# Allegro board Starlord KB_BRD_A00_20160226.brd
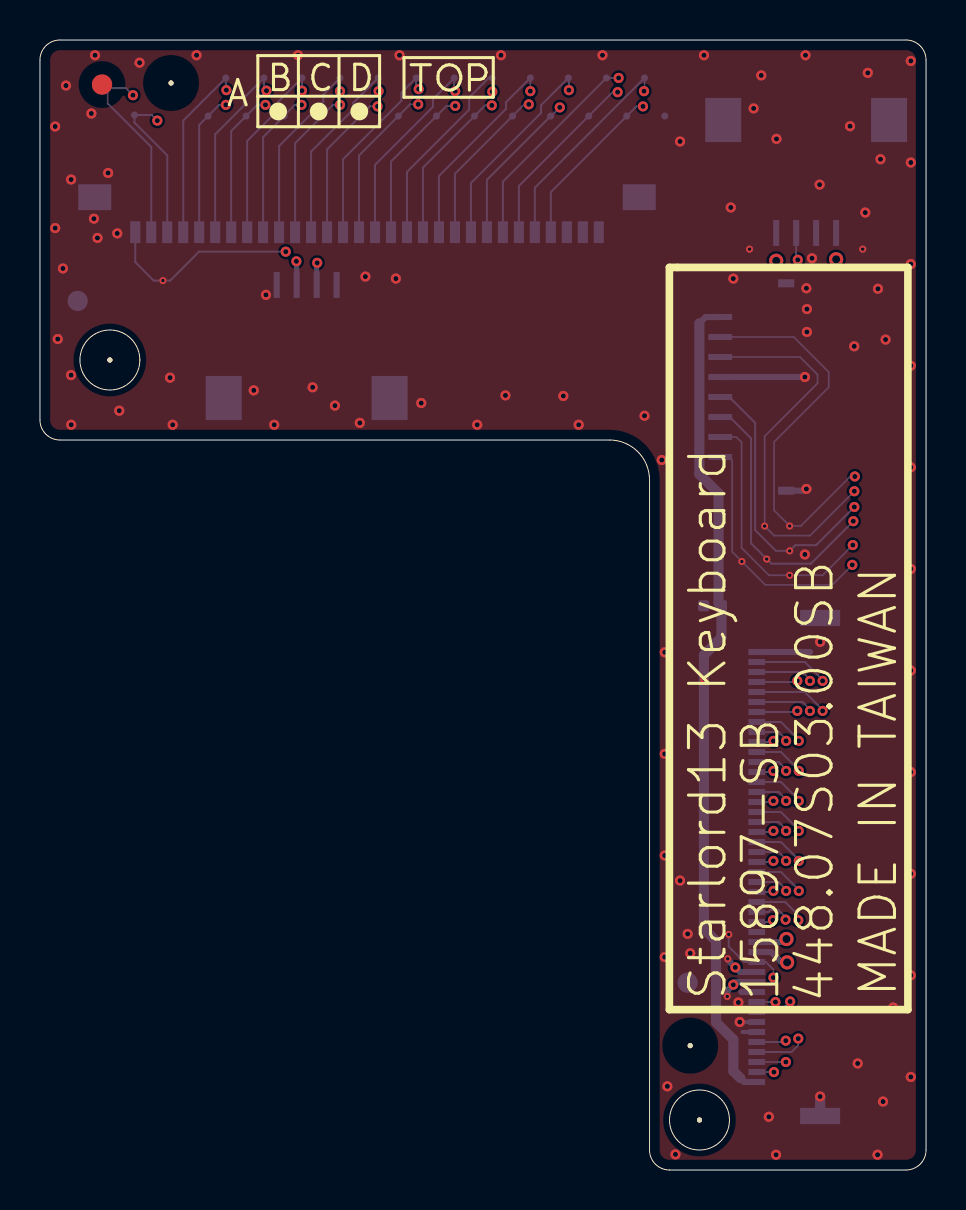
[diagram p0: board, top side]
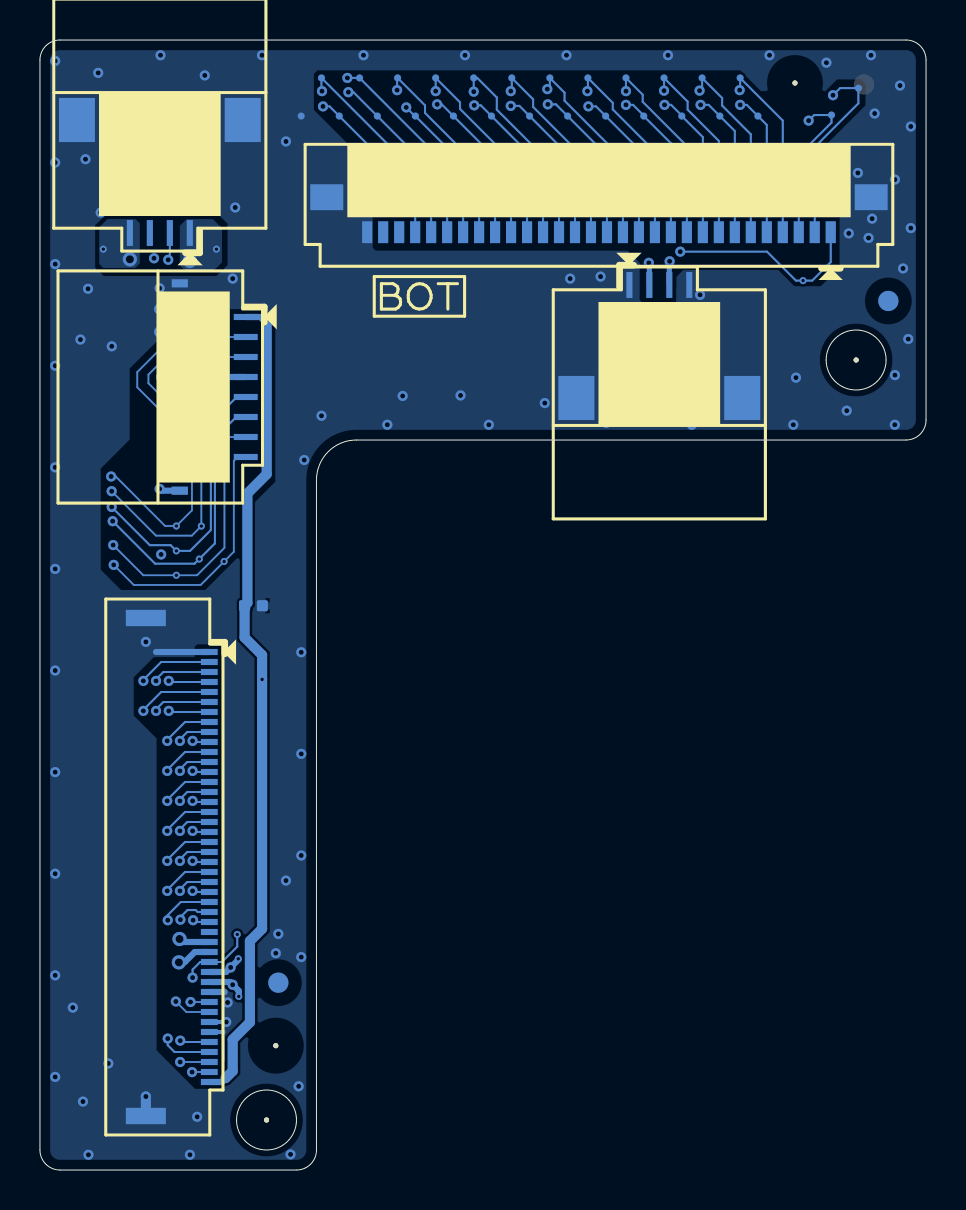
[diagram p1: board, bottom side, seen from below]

Outline 44.35 x 56.5 mm; copper layers: TOP, L2GND, L3, L4, L5VCC, L6, L7GND, BOTTOM. Coordinates in mm from the lower left corner of the outline.
Outline path: 0,55.5 0,37.5 arc(0.29,36.79) 1,36.5 28.51,36.5 arc(29.92,35.91) 30.51,34.5 30.51,1 arc(30.8,0.29) 31.51,0 43.35,0 arc(44.06,0.29) 44.35,1 44.35,55.5 arc(44.06,56.21) 43.35,56.5 1,56.5 arc(0.29,56.21) 0,55.5 ; 2,40.5 arc(3.5,42) 5,40.5 arc(3.5,39) 2,40.5 ; 31.51,2.5 arc(33.01,4) 34.51,2.5 arc(33.01,1) 31.51,2.5

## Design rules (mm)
constraint set DEFAULT: min track width 0.127, pair gap 0.102
net group LED_20MIL: nets BAT_AMBER BAT_WHITE
net group OTHER_4MIL-MWS: nets INT_TP# KB_DET# KB_LED_DET_C PTP_DIS#
net group POWER_15M: nets TP_VDD
net group SMBUS_50: nets I2C0_SCL_R I2C0_SDA_R TPCLK_C TPDATA_C
net group T4_KB-MW: nets KSI0 KSI1 KSI2 KSI3 KSI4 KSI5 KSI6 KSI7 KSO0 KSO1 KSO2 KSO3 KSO4 KSO5 KSO6 KSO7 KSO8 KSO9 KSO10 KSO11 KSO12 KSO13 KSO14 KSO15 KSO16
net group T4_LED-MWS: nets CAP_LED

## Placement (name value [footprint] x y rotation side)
AFTP201  AFTE14P-GP  [AFTE14P-75]  10.32 52.7 180 bottom
AFTP202  AFTE14P-GP  [AFTE14P-75]  3.39 54.09 180 bottom
AFTP203  AFTE14P-GP  [AFTE14P-75]  4.73 52.75 180 bottom
AFTP204  AFTE14P-GP  [AFTE14P-75]  28.35 54.6 180 bottom
AFTP205  AFTE14P-GP  [AFTE14P-75]  9.3 54.6 180 bottom
AFTP206  AFTE14P-GP  [AFTE14P-75]  11.21 54.6 180 bottom
AFTP207  AFTE14P-GP  [AFTE14P-75]  22.64 54.6 180 bottom
AFTP208  AFTE14P-GP  [AFTE14P-75]  8.42 52.7 180 bottom
AFTP209  AFTE14P-GP  [AFTE14P-75]  13.11 54.6 180 bottom
AFTP210  AFTE14P-GP  [AFTE14P-75]  15.02 54.6 180 bottom
AFTP211  AFTE14P-GP  [AFTE14P-75]  20.73 54.6 180 bottom
AFTP212  AFTE14P-GP  [AFTE14P-75]  12.23 52.7 180 bottom
AFTP213  AFTE14P-GP  [AFTE14P-75]  19.85 52.7 180 bottom
AFTP214  AFTE14P-GP  [AFTE14P-75]  14.13 52.7 180 bottom
AFTP215  AFTE14P-GP  [AFTE14P-75]  16.92 54.6 180 bottom
AFTP216  AFTE14P-GP  [AFTE14P-75]  18.83 54.6 180 bottom
AFTP217  AFTE14P-GP  [AFTE14P-75]  16.04 52.7 180 bottom
AFTP218  AFTE14P-GP  [AFTE14P-75]  17.94 52.7 180 bottom
AFTP219  AFTE14P-GP  [AFTE14P-75]  21.75 52.7 180 bottom
AFTP220  AFTE14P-GP  [AFTE14P-75]  26.45 54.6 180 bottom
AFTP221  AFTE14P-GP  [AFTE14P-75]  25.56 52.7 180 bottom
AFTP222  AFTE14P-GP  [AFTE14P-75]  27.47 52.7 180 bottom
AFTP223  AFTE14P-GP  [AFTE14P-75]  30.26 54.6 180 bottom
AFTP224  AFTE14P-GP  [AFTE14P-75]  23.66 52.7 180 bottom
AFTP225  AFTE14P-GP  [AFTE14P-75]  31.28 52.7 180 bottom
AFTP226  AFTE14P-GP  [AFTE14P-75]  29.37 52.7 180 bottom
AFTP227  AFTE14P-GP  [AFTE14P-75]  24.54 54.6 180 bottom
C201  SCD1U16V2KX-3GP  [C402H22]  33.66 28.21 90 bottom
KB1  PTWO-CON30-18-GP  [196528-30041-3]  16.37 48.64 0 bottom
KBBD2  STAR-CON44-GP  [51540-04401-W01]  39.05 15.15 270 bottom
KBBL1  ACES-CON4-66-GP  [50524-00401-001]  38.35 52.5 0 bottom
LED1  ACES-CON4-66-GP  [50524-00401-001]  13.35 38.6 180 bottom
NOREF  -  []  14.71 54.45 0 top
NOREF#2  *  [unnamed#2]  3.11 54.27 0 top
NOREF#3  -  []  20.45 54.63 0 top
NOREF#4  -  [unnamed#2]  6.56 54.35 0 top
NOREF#5  -  [unnamed#2]  3.5 40.5 0 top
NOREF#6  -  [unnamed#2]  32.55 6.22 0 top
NOREF#7  -  []  -3.65 -7.5 0 top
NOREF#8  -  []  -133.09 -45.68 0 top
NOREF#9  -  [unnamed#2]  33.01 2.5 0 top
NOREF#10  *  [unnamed#2]  32.42 9.37 180 bottom
NOREF#11  *  [unnamed#2]  1.89 43.45 180 bottom
NOREF#12  -  []  25.36 43.68 180 bottom
TP1  ACES-CON8-66-GP  [51574-0084N-W01]  37.35 39.15 270 bottom

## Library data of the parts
AFTP201-AFTP227 = AFTE14P-75: tolerance: ZZ.AFT14.101
C201 = C402H22: tolerance: 78.10421.2FL
KB1 = 196528-30041-3: tolerance: 020.K0210.0030
KBBD2 = 51540-04401-W01: tolerance: 20.K0809.044
KBBL1 LED1 = 50524-00401-001: tolerance: 020.K0037.0004
TP1 = 51574-0084N-W01: tolerance: 020.K0151.0008

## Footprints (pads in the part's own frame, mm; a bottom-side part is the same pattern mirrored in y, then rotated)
50524-00401-001
  rect 0.305x1.295 smd: 1(-1.5,5.65) 2(-0.5,5.65) 3(0.5,5.65) 4(1.5,5.65)
  rect 1.803x2.21 smd: 5(-4.15,0) 6(4.15,0)
51540-04401-W01
  rect 0.305x0.838 smd: 1(-10.75,3.175) 2(-10.25,3.175) 3(-9.75,3.175) 4(-9.25,3.175) 5(-8.75,3.175) 6(-8.25,3.175) 7(-7.75,3.175) 8(-7.25,3.175) 9(-6.75,3.175) 10(-6.25,3.175) 11(-5.75,3.175) 12(-5.25,3.175) 13(-4.75,3.175) 14(-4.25,3.175) 15(-3.75,3.175) 16(-3.25,3.175) 17(-2.75,3.175) 18(-2.25,3.175) 19(-1.75,3.175) 20(-1.25,3.175) 21(-0.75,3.175) 22(-0.25,3.175) 23(0.25,3.175) 24(0.75,3.175) 25(1.25,3.175) 26(1.75,3.175) 27(2.25,3.175) 28(2.75,3.175) 29(3.25,3.175) 30(3.75,3.175) 31(4.25,3.175) 32(4.75,3.175) 33(5.25,3.175) 34(5.75,3.175) 35(6.25,3.175) 36(6.75,3.175) 37(7.25,3.175) 38(7.75,3.175) 39(8.25,3.175) 40(8.75,3.175) 41(9.25,3.175) 42(9.75,3.175) 43(10.25,3.175) 44(10.75,3.175)
  rect 0.813x2.007 smd: 45(-12.45,0) 46(12.45,0)
51574-0084N-W01
  rect 0.305x1.194 smd: 1(-3.5,3.3) 2(-2.5,3.3) 3(-1.5,3.3) 4(-0.5,3.3) 5(0.5,3.3) 6(1.5,3.3) 7(2.5,3.3) 8(3.5,3.3)
  rect 0.406x0.813 smd: 9(-5.185,0) 10(5.185,0)
196528-30041-3
  rect 0.508x1.092 smd: 1(-11.6,1.75) 2(-10.8,1.75) 3(-10,1.75) 4(-9.2,1.75) 5(-8.4,1.75) 6(-7.6,1.75) 7(-6.8,1.75) 8(-6,1.75) 9(-5.2,1.75) 10(-4.4,1.75) 11(-3.6,1.75) 12(-2.8,1.75) 13(-2,1.75) 14(-1.2,1.75) 15(-0.4,1.75) 16(0.4,1.75) 17(1.2,1.75) 18(2,1.75) 19(2.8,1.75) 20(3.6,1.75) 21(4.4,1.75) 22(5.2,1.75) 23(6,1.75) 24(6.8,1.75) 25(7.6,1.75) 26(8.4,1.75) 27(9.2,1.75) 28(10,1.75) 29(10.8,1.75) 30(11.6,1.75)
  rect 1.651x1.295 smd: 31(-13.625,0) 32(13.625,0)
AFTE14P-75
  round 0.356 smd: 1(0,0)
C402H22
  custom 0.14x0.14 smd: 1(0,0.445) 2(0,-0.445)
unnamed#2
  round 1.016 smd: (0,0)

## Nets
+5V_KB_BL: KBBD2.30 KBBL1.1
GND: AFTP225.1 C201.2 KB1.30 KB1.31 KB1.32 KBBD2.1 KBBD2.35 KBBD2.38 KBBD2.39 KBBD2.45 KBBD2.46 KBBL1.5 KBBL1.6 LED1.1 LED1.4 LED1.5 LED1.6 TP1.4 TP1.9 TP1.10
BAT_AMBER: KBBD2.33 LED1.2
BAT_WHITE: KBBD2.34 LED1.3
CAP_LED: AFTP226.1 KB1.27 KBBD2.2
I2C0_SCL_R: KBBD2.37 TP1.3
I2C0_SDA_R: KBBD2.36 TP1.2
INT_TP#: KBBD2.40 TP1.5
KB_BL_CTRL#: KBBD2.31 KBBL1.4
KB_DET#: KB1.1 KBBD2.28
KB_LED_DET_C: KBBD2.32 KBBL1.2
KSI0: AFTP212.1 KB1.9 KBBD2.20
KSI1: AFTP201.1 KB1.7 KBBD2.22
KSI2: AFTP208.1 KB1.5 KBBD2.24
KSI3: AFTP209.1 KB1.8 KBBD2.21
KSI4: AFTP205.1 KB1.4 KBBD2.25
KSI5: AFTP206.1 KB1.6 KBBD2.23
KSI6: AFTP203.1 KB1.3 KBBD2.26
KSI7: AFTP202.1 KB1.2 KBBD2.27
KSO0: AFTP207.1 KB1.18 KBBD2.11
KSO1: AFTP211.1 KB1.16 KBBD2.13
KSO2: AFTP213.1 KB1.17 KBBD2.12
KSO3: AFTP218.1 KB1.15 KBBD2.14
KSO4: AFTP214.1 KB1.11 KBBD2.18
KSO5: AFTP210.1 KB1.10 KBBD2.19
KSO6: AFTP217.1 KB1.13 KBBD2.16
KSO7: AFTP215.1 KB1.12 KBBD2.17
KSO8: AFTP216.1 KB1.14 KBBD2.15
KSO9: AFTP204.1 KB1.24 KBBD2.5
KSO10: AFTP223.1 KB1.26 KBBD2.3
KSO11: AFTP222.1 KB1.25 KBBD2.4
KSO12: AFTP219.1 KB1.19 KBBD2.10
KSO13: AFTP220.1 KB1.22 KBBD2.7
KSO14: AFTP221.1 KB1.23 KBBD2.6
KSO15: AFTP224.1 KB1.21 KBBD2.8
KSO16: AFTP227.1 KB1.20 KBBD2.9
PTP_DIS#: KBBD2.41 TP1.6
TP_VDD: C201.1 KBBD2.44 TP1.1
TPCLK_C: KBBD2.43 TP1.8
TPDATA_C: KBBD2.42 TP1.7

Pads without a net: KB1 28 29; KBBD2 29; KBBL1 3

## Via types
v1: diameter 0.356, hole 0.178, TOP to BOTTOM, 13 vias
v2: diameter 0.508, hole 0.254, TOP to BOTTOM, 163 vias
v3: diameter 0.711, hole 0.406, TOP to BOTTOM, 4 vias

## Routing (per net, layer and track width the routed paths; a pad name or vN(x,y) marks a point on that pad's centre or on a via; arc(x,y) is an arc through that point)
+5V_KB_BL: length 39.6
  L3 w1.016: v3(37.36,11.55) 39.28,11.55 40.8,13.07 40.8,26.46 36.85,30.41 v3(36.85,45.46)
  BOTTOM w0.305: KBBD2.30 37.21,11.4 v3(37.36,11.55)
  vias: v1(35.52,46.04)
GND: length 11.3
  BOTTOM w0.203: 35.16,6.9 KBBD2.39 ; KBBD2.38 v2(35.02,7.4)
  BOTTOM w0.305: v2(38.36,34.05) 38.27,33.96 TP1.10 ; 35.1,8.9 KBBD2.35 ; 38.54,25.9 KBBD2.1 ; TP1.4 v2(38.29,39.65)
  BOTTOM w0.508: KBBD2.46 v2(39.05,3.67)
  vias: v2(0.76,52.18) v2(0.76,47.1) v2(0.89,41.55) v2(1.15,45.08) v2(1.3,54.22) v2(1.56,49.52) v2(1.56,39.74) v2(1.56,37.26) v2(2.57,52.82) v2(2.7,47.57) v2(2.76,55.74) v2(2.88,46.6) v2(3.41,49.85) v2(3.87,46.83) v2(3.97,37.97) v2(4.99,55.36) v2(6.51,39.62) v2(6.64,37.26) v2(7.84,55.74) v2(10.7,38.98) v2(11.31,43.76) v2(11.72,37.26) v2(12.92,55.74) v2(13.65,39.13) v2(14.77,38.22) v2(16.01,37.36) v2(16.29,44.67) v2(17.81,44.57) v2(18,55.74) v2(19.08,38.35) v2(21.88,37.26) v2(23.08,55.74) v2(23.3,38.73) v2(26.2,38.7) v2(26.96,37.26) v2(28.16,55.74) v2(30.26,37.71) v2(31.12,35.5) v2(31.27,25.89) v2(31.27,20.81) v2(31.27,15.73) v2(31.27,10.65) v2(31.4,4.18) v2(31.81,0.78) v2(32.04,51.43) v2(32.04,14.47) v2(32.42,11.8) v2(32.55,10.84) v2(33.24,55.74) v2(34.58,48.13) v2(34.7,44.57) v2(34.96,8.37) v2(35.72,53.08) v2(36.1,54.73) v2(36.48,2.66) v2(36.86,51.55) v2(36.84,0.76) v2(38.29,30.78) v2(38.32,55.74) v2(38.36,44.09) v2(38.39,43.05) v2(38.39,41.9) v2(38.64,45.59) v2(39.02,49.27) v2(39.05,26.41) v2(40.55,52.19) v2(40.76,41.18) v2(40.93,5.33) v2(41.31,47.87) v2(41.44,54.86) v2(41.94,44.06) v2(41.92,0.76) v2(42.07,50.54) v2(42.2,3.42) v2(42.32,41.52) v2(42.71,8.12) v2(43.59,55.45) v2(43.59,50.37) v2(43.59,45.29) v2(43.59,40.21) v2(43.59,35.13) v2(43.59,30.05) v2(43.59,24.97) v2(43.59,19.89) v2(43.59,14.81) v2(43.59,9.73) v2(43.59,4.65)
BAT_AMBER: length 53.9
  L3 w0.508: v2(34.81,10.13) 34.59,10.34 34.59,35.45 30,40.05 17.88,40.05 13.88,44.05 v2(13.88,45.36)
  BOTTOM w0.254: LED1.2 13.85,45.33 v2(13.88,45.36)
  BOTTOM w0.305: KBBD2.33 35.03,9.9 v2(34.81,10.13) 34.42,10.51 v1(34.42,10.56)
BAT_WHITE: length 55.5
  L3 w0.508: v2(12.83,45.43) 12.83,44.09 17.51,39.41 29.73,39.41 33.87,35.28 33.87,10.1 v2(34.7,9.26)
  BOTTOM w0.254: v2(12.83,45.43) 12.85,45.42 LED1.3
  BOTTOM w0.305: v1(34.4,8.68) 34.4,8.96 v2(34.7,9.26) 34.84,9.4 KBBD2.34
CAP_LED: length 44.6
  L6 w0.102: v2(39.17,24.46) 37.83,25.8 37.83,39.74 30.18,47.39 v2(30.18,53.18)
  BOTTOM w0.102: v2(39.17,24.46) 39.17,24.51 38.28,25.4 KBBD2.2 ; v2(30.18,53.18) 29.85,53.18 AFTP226.1 25.57,48.9 KB1.27
I2C0_SCL_R: length 49.8
  L6 w0.102: v2(40.76,33.94) 39.96,33.14 39.96,29.83 40.98,28.82 40.98,10.56 39.07,8.65 37.78,8.65 v2(37.55,8.43)
  BOTTOM w0.089: KBBD2.37 37.02,7.9 v2(37.55,8.43) ; v2(40.76,33.94) 38.54,31.72 36.75,31.72 v1(36.27,32.2) 36.27,36.69 38.92,39.34 38.92,39.77 38.04,40.65 TP1.3
I2C0_SDA_R: length 50.1
  L6 w0.102: v2(36.81,8.4) 36.84,8.4 37.58,9.14 38.87,9.14 40.5,10.76 40.5,28.62 39.48,29.63 39.48,33.37 v2(40.79,34.68)
  BOTTOM w0.089: KBBD2.36 v2(36.81,8.4) ; v2(40.79,34.68) 40.56,34.68 38.08,32.2 v1(37.52,32.2) 36.74,32.98 36.74,36.4 39.48,39.13 39.48,39.9 37.73,41.65 TP1.2
INT_TP#: length 46.6
  L6 w0.102: v2(37.33,6.47) 37.77,6.03 38.83,6.03 42.63,9.83 42.63,31.28 v2(40.76,33.15)
  BOTTOM w0.102: v2(40.76,33.15) 38.85,31.24 37.81,31.24 v1(37.52,30.96) 36.84,30.96 35.8,32 35.8,37.36 34.5,38.65 TP1.5 ; KBBD2.40 37.26,6.4 v2(37.33,6.47)
KB_BL_CTRL#: length 41.7
  L3 w1.016: v3(37.4,10.38) 40.01,10.38 42.07,12.44 42.07,27.04 39.35,29.76 39.35,45.04 v3(39.85,45.54)
  BOTTOM w0.305: v3(37.4,10.38) 37.37,10.41 37.09,10.41 36.6,10.9 KBBD2.31
  vias: v1(41.18,46.04)
KB_DET#: length 61.2
  L6 w0.102: v2(36.69,12.49) 31.88,17.29 31.88,37.28 22.77,46.4 12.78,46.4 v2(12.3,45.92)
  BOTTOM w0.102: v2(12.3,45.92) 7.96,45.92 6.51,44.47 v1(6.15,44.47) 5.7,44.47 4.77,45.4 KB1.1 ; v2(36.69,12.49) 36.6,12.4 KBBD2.28
KB_LED_DET_C: length 44.2
  L6 w0.102: v2(36.71,9.62) 38.67,9.62 39.84,10.79 39.84,28.46 39,29.3 39,44.44 v2(37.93,45.51)
  BOTTOM w0.102: v2(36.71,9.62) 36.71,10.02 36.33,10.4 KBBD2.32 35.24,10.4 34.48,11.17 v1(34.48,11.78) ; KBBL1.2 37.85,45.59 v2(37.93,45.51)
KSI0: length 61.6
  L6 w0.102: v2(37.98,15.45) 37.11,16.33 36.73,16.33 33.71,19.34 33.71,38.04 23.22,48.53 17.43,48.53 13.09,52.88 v2(13.09,53.26)
  BOTTOM w0.102: v2(37.98,15.45) 37.98,15.51 37.09,16.4 KBBD2.20 ; KB1.9 11.17,51.64 AFTP212.1 12.23,52.72 12.76,53.26 v2(13.09,53.26)
KSI1: length 60.4
  L6 w0.102: v2(11.29,53.26) 16.54,48 23.11,48 33.26,37.85 33.26,18.91 v2(36.71,15.45)
  BOTTOM w0.102: v2(11.29,53.26) 10.88,53.26 AFTP201.1 9.57,51.95 KB1.7 ; KBBD2.22 36.66,15.4 v2(36.71,15.45)
KSI2: length 64.4
  L6 w0.102: v2(37.35,13.95) 36.91,14.39 36.84,14.39 32.8,18.43 32.8,37.66 22.99,47.47 15.1,47.47 v2(9.3,53.26)
  BOTTOM w0.102: KB1.5 7.97,52.25 AFTP208.1 8.97,53.26 v2(9.3,53.26) ; KBBD2.24 36.98,14.4 37.32,14.06 37.32,13.98 v2(37.35,13.95)
KSI3: length 63.5
  L6 w0.102: v2(37.35,15.45) 36.7,16.1 36.63,16.1 33.48,19.25 33.48,37.94 23.18,48.25 17.39,48.25 12.66,52.98 12.66,53.51 v2(13.11,53.97)
  BOTTOM w0.102: v2(37.35,15.45) 37.32,15.48 37.32,15.56 36.98,15.9 KBBD2.21 ; KB1.8 10.37,51.45 11.93,53.02 11.93,53.42 AFTP209.1 v2(13.11,53.97)
KSI4: length 66.8
  L6 w0.102: v2(36.71,13.95) 32.57,18.09 32.57,37.57 22.97,47.16 14.47,47.16 8.87,52.76 8.87,53.54 v2(9.33,53.99)
  BOTTOM w0.102: KB1.4 7.17,52.47 AFTP205.1 9.3,54.02 v2(9.33,53.99) ; KBBD2.25 35.88,13.9 36.66,13.9 v2(36.71,13.95)
KSI5: length 67.6
  L6 w0.102: v2(11.34,53.97) 10.85,53.49 10.85,53.08 16.19,47.74 23.04,47.74 33.03,37.75 33.03,18.53 36.53,15.02 36.91,15.02 v2(37.98,13.95)
  BOTTOM w0.102: v2(11.34,53.97) 11.21,54.09 AFTP206.1 10.21,53.6 10.21,53.22 8.77,51.78 KB1.6 ; v2(37.98,13.95) 37.98,14.01 37.09,14.9 35.88,14.9 KBBD2.23
KSI6: length 70.6
  L6 w0.102: v2(5.88,52.47) 8.77,52.47 14.31,46.93 22.88,46.93 32.34,37.47 32.34,17.71 36.6,13.45 36.99,13.45 37.75,12.7 37.75,12.69 v2(37.95,12.49)
  BOTTOM w0.102: v2(5.88,52.47) 5.6,52.75 AFTP203.1 4.73,52.37 6.37,50.73 KB1.3 ; KBBD2.26 37.3,13.4 37.95,12.74 v2(37.95,12.49)
KSI7: length 73.1
  L6 w0.102: v2(4.66,53.74) 5.19,53.21 5.19,52.52 5.7,52.01 8.77,52.01 14.16,46.63 22.86,46.63 32.11,37.38 32.11,36.16 32.11,36.16 32.11,17.47 36.36,13.23 36.61,13.23 v2(37.32,12.52)
  BOTTOM w0.102: KB1.2 5.57,51.15 3.39,53.33 AFTP202.1 4.3,54.09 v2(4.66,53.74) ; v2(37.32,12.52) 37.32,12.64 36.97,13 36.56,13 36.46,12.9 KBBD2.27
KSO0: length 53.7
  L6 w0.102: v2(37.98,19.95) 37.24,20.69 36.86,20.69 35.77,21.78 35.77,38.89 22.16,52.51 22.16,53.43 v2(22.64,53.92)
  BOTTOM w0.102: v2(22.64,53.92) AFTP207.1 22.46,54.6 21.48,53.62 21.48,53.02 18.37,49.9 KB1.18 ; KBBD2.11 35.88,20.9 37.09,20.9 37.98,20.01 v2(37.98,19.95)
KSO1: length 52.2
  L6 w0.102: v2(20.78,53.94) 20.35,53.51 20.35,53.03 23.25,50.13 23.88,50.13 35.31,38.7 35.31,21.35 v2(36.71,19.95)
  BOTTOM w0.102: KB1.16 16.77,50.26 19.67,53.16 19.67,53.54 AFTP211.1 20.73,53.99 v2(20.78,53.94) ; v2(36.71,19.95) 36.66,19.9 35.88,19.9 KBBD2.13
KSO2: length 50
  L6 w0.102: v2(20.78,53.21) 21.13,53.21 35.54,38.8 35.54,21.69 36.77,20.47 36.84,20.47 v2(37.35,19.95)
  BOTTOM w0.102: KB1.17 17.57,50.42 AFTP213.1 20.35,53.21 v2(20.78,53.21) ; v2(37.35,19.95) 37.32,19.98 37.32,20.06 36.98,20.4 KBBD2.12
KSO3: length 54.2
  L6 w0.102: v2(18.93,53.28) 22.31,49.9 23.79,49.9 35.09,38.61 35.09,20.97 36.86,19.2 37.24,19.2 v2(37.98,18.45)
  BOTTOM w0.102: KBBD2.14 37.09,19.4 37.98,18.51 v2(37.98,18.45) ; KB1.15 15.97,50.73 AFTP218.1 18.52,53.28 v2(18.93,53.28)
KSO4: length 57.6
  L6 w0.102: v2(37.35,16.95) 36.55,17.75 36.48,17.75 34.17,20.06 34.17,38.23 23.41,48.99 18.68,48.99 15.02,52.65 v2(15.02,53.26)
  BOTTOM w0.102: v2(37.35,16.95) 37.32,16.98 37.32,17.06 36.98,17.4 KBBD2.18 ; v2(15.02,53.26) 14.66,53.26 14.13,52.72 AFTP214.1 12.77,51.34 KB1.11
KSO5: length 59.6
  L6 w0.102: v2(36.71,16.95) 33.94,19.72 33.94,38.13 23.31,48.76 18.58,48.76 14.59,52.76 14.59,53.51 v2(15.02,53.94)
  BOTTOM w0.102: KB1.10 11.97,51.2 14.18,53.41 14.18,53.76 AFTP210.1 v2(15.02,53.94) ; v2(36.71,16.95) 36.66,16.9 35.88,16.9 KBBD2.19
KSO6: length 53.1
  L6 w0.102: v2(16.9,53.18) 20.63,49.45 23.6,49.45 34.63,38.42 34.63,20.54 v2(36.71,18.45)
  BOTTOM w0.102: KB1.13 14.37,51.03 AFTP217.1 16.52,53.18 v2(16.9,53.18) ; KBBD2.16 36.66,18.4 v2(36.71,18.45)
KSO7: length 60.5
  L6 w0.102: v2(37.98,16.95) 36.96,17.98 36.58,17.98 34.4,20.16 34.4,38.32 23.5,49.22 20.25,49.22 16.47,53 16.47,53.46 v2(16.95,53.94)
  BOTTOM w0.102: KBBD2.17 35.88,17.9 37.09,17.9 37.98,17.01 v2(37.98,16.95) ; v2(16.95,53.94) 16.92,53.97 AFTP215.1 15.68,53.36 15.68,53.03 13.57,50.92 KB1.12
KSO8: length 56.2
  L6 w0.102: v2(18.96,54.04) 18.5,53.59 18.5,53.1 21.93,49.68 23.69,49.68 34.86,38.51 34.86,20.87 36.76,18.97 36.83,18.97 v2(37.35,18.45)
  BOTTOM w0.102: v2(37.35,18.45) 37.32,18.48 37.32,18.56 36.98,18.9 KBBD2.15 ; KB1.14 15.17,50.54 18.09,53.46 18.09,53.87 AFTP216.1 18.83,54.17 v2(18.96,54.04)
KSO9: length 50.9
  L6 w0.102: v2(28.96,54.6) 28.28,53.92 28.28,48.32 37.14,39.46 37.14,24.61 37.96,23.79 38.34,23.79 v2(39.17,22.95)
  BOTTOM w0.102: v2(28.96,54.6) AFTP204.1 23.17,49.42 KB1.24 ; KBBD2.5 38.28,23.9 39.17,23.01 v2(39.17,22.95)
KSO10: length 46.9
  L6 w0.102: v2(38.54,24.46) 37.6,25.39 37.6,39.65 29.67,47.57 29.67,53.38 v2(30.23,53.94)
  BOTTOM w0.102: v2(38.54,24.46) 38.51,24.48 38.51,24.56 38.17,24.9 KBBD2.3 ; v2(30.23,53.94) 30.26,53.97 AFTP223.1 24.77,49.11 KB1.26
KSO11: length 44.4
  L6 w0.102: v2(28.91,53.89) 28.91,48.01 37.37,39.55 37.37,24.99 v2(37.9,24.46)
  BOTTOM w0.102: v2(28.91,53.89) 28.66,53.89 AFTP222.1 23.97,49.2 KB1.25 ; KBBD2.4 35.88,24.4 37.85,24.4 v2(37.9,24.46)
KSO12: length 46.4
  L6 w0.102: v2(36.71,21.45) 36,22.17 36,38.99 22.61,52.38 22.61,53.23 v2(22.61,53.23)
  BOTTOM w0.102: v2(36.71,21.45) 36.66,21.4 KBBD2.10 ; v2(22.61,53.23) 22.28,53.23 AFTP219.1 19.17,50.12 KB1.19
KSO13: length 49.1
  L6 w0.102: v2(26.47,53.99) 26.17,53.99 25.53,53.36 25.53,50.42 36.69,39.27 36.69,24.17 v2(37.9,22.95)
  BOTTOM w0.102: v2(26.47,53.99) 26.47,54.58 AFTP220.1 25.08,53.23 25.08,52.85 21.57,49.35 KB1.22 ; v2(37.9,22.95) 37.85,22.9 KBBD2.7
KSO14: length 46.1
  L6 w0.102: v2(26.02,53.13) 26.02,50.26 36.91,39.37 36.91,24.51 37.86,23.56 37.93,23.56 v2(38.54,22.95)
  BOTTOM w0.102: KBBD2.6 35.88,23.4 38.17,23.4 38.51,23.06 38.51,22.98 v2(38.54,22.95) ; v2(26.02,53.13) 25.59,52.7 AFTP221.1 22.37,49.51 KB1.23
KSO15: length 48
  L6 w0.102: v2(37.98,21.45) 36.46,22.98 36.46,39.18 24.47,51.16 v2(24.47,53.28)
  BOTTOM w0.102: v2(37.98,21.45) 37.98,21.51 37.09,22.4 KBBD2.8 ; v2(24.47,53.28) 24.24,53.28 AFTP224.1 20.77,49.81 KB1.21
KSO16: length 50.2
  L6 w0.102: v2(24.54,53.94) 24.52,53.94 24.04,53.46 24.04,51.27 36.23,39.08 36.23,22.57 v2(37.35,21.45)
  BOTTOM w0.102: KB1.20 19.97,49.7 23.32,53.06 23.32,53.38 AFTP227.1 v2(24.54,53.94) ; v2(37.35,21.45) 37.32,21.48 37.32,21.56 36.98,21.9 KBBD2.9
PTP_DIS#: length 45.3
  L6 w0.102: v2(40.71,32.44) 42.43,30.72 42.43,9.91 39.08,6.57 v2(37.96,6.57)
  BOTTOM w0.102: v2(40.71,32.44) 38.58,30.31 36.62,30.31 36.38,30.55 v1(36.38,30.55) 35.59,31.33 35.59,36.58 34.53,37.65 TP1.6 ; KBBD2.41 37.61,5.9 37.96,6.24 v2(37.96,6.57)
TP_VDD: length 41.4
  BOTTOM w0.305: TP1.1 33.32,42.65 33,42.33 ; 35.06,4.59 35.25,4.4 KBBD2.44
  BOTTOM w0.508: 35.06,4.59 34.7,4.95 34.7,6.52 33.84,7.38 33.84,11.45 33.23,12.06 v1(33.23,24.53) 33.23,25.75 34.11,26.62 C201.1 33.97,28.35 33.97,33.83 33,34.79 33,42.33
TPCLK_C: length 42.1
  L6 w0.102: v2(40.66,30.26) 41.46,29.45 41.46,10.36 38.92,7.82 37.22,7.82 36.41,7 36.41,5.23 v2(36.74,4.9)
  BOTTOM w0.089: KBBD2.43 36.73,4.9 v2(36.74,4.9) ; v2(40.66,30.26) 39.66,29.25 36.3,29.25 v1(35.13,30.43) 34.65,30.91 34.65,35.46 34.45,35.65 TP1.8
TPDATA_C: length 44.3
  L6 w0.102: v2(40.68,31.25) 41.94,29.99 41.94,10.16 39.12,7.33 38.72,7.33 37.42,7.33 36.9,6.81 36.9,5.84 v2(37.33,5.4)
  BOTTOM w0.089: v2(40.68,31.25) 39.17,29.74 v1(37.52,29.74) 36.49,29.74 35.12,31.11 35.12,36.38 34.85,36.65 TP1.7 ; KBBD2.42 v2(37.33,5.4)

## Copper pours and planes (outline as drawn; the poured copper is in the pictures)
+5V_KB_BL on BOTTOM: 35.69,47.54 37.02,47.54 37.35,47.21 37.35,45.23 37.04,44.93 35.69,44.93 35.24,45.38 35.24,47.08
GND on TOP, L2GND, L5VCC, L7GND: 31.51,0.51 31.16,0.65 31.02,1 31.02,34.5 30.28,36.27 28.51,37.01 1,37.01 0.65,37.15 0.51,37.5 0.51,55.5 0.65,55.85 1,55.99 43.35,55.99 43.7,55.85 43.84,55.5 43.84,1 43.7,0.65 43.35,0.51
GND on BOTTOM: 31.51,0.51 31.16,0.65 31.02,1 31.02,34.5 30.28,36.27 28.51,37.01 1,37.01 0.65,37.15 0.51,37.5 0.51,55.5 0.65,55.85 1,55.99 43.35,55.99 43.7,55.85 43.84,55.5 43.84,1 43.7,0.65 43.35,0.51 ; 6 cut-outs
GND on L6: 31.51,0.51 31.16,0.65 31.02,1 31.02,34.5 30.28,36.27 28.51,37.01 1,37.01 0.65,37.15 0.51,37.5 0.51,55.5 0.65,55.85 1,55.99 43.35,55.99 43.7,55.85 43.84,55.5 43.84,1 43.7,0.65 43.35,0.51 ; 1 cut-out
KB_BL_CTRL# on BOTTOM: 39.56,47.54 40.98,47.54 41.38,47.14 41.38,45.31 41.18,45.1 39.58,45.1 39.35,45.33 39.35,47.34

Small or netless copper shapes (teardrops, artwork), in the pictures only: 1 on L3

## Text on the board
Ref Des/Silkscreen Top: Starlord13 Keyboard | 15897-SB | 448.07S03.00SB | MADE IN TAIWAN
User.31: ByImpedance:100.0@_REF_L1=("nil(L1)")|_REF_L6=("4.0/10.0(L6)")|Type="DP"|_REF_L4=("4.0/6.5(L4)")|_REF_L3=("4.0/6.5(L3)" "4.0/10.0(L3)")|imp="100.0"|_REF_L8=("nil(L8)") | ByImpedance:33.0@_REF_L1=("8.0(L1)")|_REF_L6=("9.0(L6)")|Type="SE"|_REF_L4=("11.0(L4)")|_REF_L3=("11.0(L3)" "9.0(L3)")|imp="33.0"|_REF_L8=("8.0(L8)") | ByImpedance:35.0@_REF_L1=("7.5(L1)")|_REF_L6=("8.5(L6)")|Type="SE"|_REF_L4=("10.0(L4)")|_REF_L3=("10.0(L3)" "8.5(L3)")|imp="35.0"|_REF_L8=("7.5(L8)") | ByImpedance:37.5@_REF_L1=("6.5(L1)")|_REF_L6=("7.5(L6)")|Type="SE"|_REF_L4=("9.0(L4)")|_REF_L3=("7.5(L3)" "9.0(L3)")|imp="37.5"|_REF_L8=("6.5(L8)") | ByImpedance:40.0@_REF_L1=("6.0(L1)")|_REF_L6=("6.5(L6)")|Type="SE"|_REF_L4=("8.0(L4)")|_REF_L3=("6.5(L3)" "8.0(L3)")|imp="40.0"|_REF_L8=("6.0(L8)") | ByImpedance:45.0@_REF_L1=("4.5(L1)")|_REF_L6=("5.0(L6)")|Type="SE"|_REF_L4=("6.5(L4)")|_REF_L3=("6.5(L3)" "5.0(L3)")|imp="45.0"|_REF_L8=("4.5(L8)") | ByImpedance:50.0@_REF_L1=("3.5(L1)")|_REF_L6=("4.0(L6)")|Type="SE"|_REF_L4=("5.0(L4)")|_REF_L3=("4.0(L3)" "5.0(L3)")|imp="50.0"|_REF_L8=("3.5(L8)") | ByImpedance:55.0@_REF_L1=("nil(L1)")|_REF_L6=("nil(L6)")|Type="SE"|_REF_L4=("4.0(L4)")|_REF_L3=("4.0(L3)")|imp="55.0"|_REF_L8=("nil(L8)") | ByImpedance:60.0@_REF_L1=("7.5/4.0(L1)")|_REF_L6=("9.5/4.5(L6)")|Type="DP"|_REF_L4=("10.5/4.5(L4)")|_REF_L3=("10.5/4.5(L3)" "9.5/4.5(L3)")|imp="60.0"|_REF_L8=("7.5/4.0(L8)") | ByImpedance:63.0@_REF_L1=("7.0/4.5(L1)")|_REF_L6=("8.5/4.0(L6)")|Type="DP"|_REF_L4=("9.5/4.0(L4)")|_REF_L3=("8.5/4.0(L3)" "9.5/4.0(L3)")|imp="63.0"|_REF_L8=("7.0/4.5(L8)") | ByImpedance:70.0@_REF_L1=("6.0/5.0(L1)")|_REF_L6=("7.0/5.0(L6)")|Type="DP"|_REF_L4=("8.5/5.0(L4)")|_REF_L3=("7.0/5.0(L3)" "8.5/5.0(L3)")|imp="70.0"|_REF_L8=("6.0/5.0(L8)") | ByImpedance:72.0@_REF_L1=("5.5/4.5(L1)")|_REF_L6=("6.5/4.5(L6)")|Type="DP"|_REF_L4=("7.5/5.0(L4)")|_REF_L3=("7.5/5.0(L3)" "6.5/4.5(L3)")|imp="72.0"|_REF_L8=("5.5/4.5(L8)") | ByImpedance:75.0@_REF_L1=("5.0/4.5(L1)")|_REF_L6=("6.0/4.5(L6)")|Type="DP"|_REF_L4=("7.0/5.0(L4)")|_REF_L3=("7.0/5.0(L3)" "6.0/4.5(L3)")|imp="75.0"|_REF_L8=("5.0/4.5(L8)") | ByImpedance:80.0@_REF_L1=("4.5/5.0(L1)")|_REF_L6=("5.5/5.0(L6)")|Type="DP"|_REF_L4=("6.0/5.0(L4)")|_REF_L3=("5.5/5.0(L3)" "6.0/5.0(L3)")|imp="80.0"|_REF_L8=("4.5/5.0(L8)") | ByImpedance:83.0@_REF_L1=("3.5/4.0(L1)")|_REF_L6=("5.0/4.0(L6)")|Type="DP"|_REF_L4=("5.5/4.5(L4)")|_REF_L3=("5.5/4.5(L3)" "5.0/4.0(L3)")|imp="83.0"|_REF_L8=("3.5/4.0(L8)") | ByImpedance:85.0@_REF_L1=("4.0/5.0(L1)")|_REF_L6=("5.0/5.5(L6)")|Type="DP"|_REF_L4=("5.5/5.0(L4)")|_REF_L3=("5.5/5.0(L3)" "5.0/5.5(L3)")|imp="85.0"|_REF_L8=("4.0/5.0(L8)") | ByImpedance:88.0@_REF_L1=("4.0/7.0(L1)")|_REF_L6=("4.0/4.0(L6)")|Type="DP"|_REF_L4=("5.0/5.0(L4)")|_REF_L3=("4.0/4.0(L3)" "5.0/5.0(L3)")|imp="88.0"|_REF_L8=("4.0/7.0(L8)") | ByImpedance:90.0@_REF_L1=("4.0/8.0(L1)" "3.5/6.0(L1)")|_REF_L6=("4.0/4.5(L6)")|Type="DP"|_REF_L4=("5.0/6.0(L4)")|_REF_L3=("5.0/6.0(L3)" "4.0/4.5(L3)")|imp="90.0"|_REF_L8=("4.0/8.0(L8)" "3.5/6.0(L8)") | LayerIndex:nil | Source:8-1.0-16f.xls | artWorks:("_REF_L3" "_REF_L6" "_REF_L4" "_REF_L8" "_REF_L1") | gtImpOutlineUsed:BOARD GEOMETRY/OUTLINE
User.32: Board Accuracy Check,Dec 02 10:44:27 2015,Passed | Dummy-Static-No Shape On Layer Check,Dec 02 10:44:27 2015,Passed | Split Plane Check,Oct 21 09:39:32 2015,Passed
User.34: This gerber is just for your reference to find the DP impedance traces in layer L1. | DP IMPEDANCE TABLE: L1 | * - Denotes that this Impedance | is NOT used | IMP(Ohm) | *60.0 | *63.0 | *70.0 | *72.0 | *75.0 | *80.0 | *83.0 | *85.0 | *88.0 | *90.0 | *100.0 | WIDTH(mils) | 7.5/4.0 | 7.0/4.5 | 6.0/5.0 | 5.5/4.5 | 5.0/4.5 | 4.5/5.0 | 3.5/4.0 | 4.0/5.0 | 4.0/7.0 | 4.0/8.0 | 3.5/6.0 | nil | TYPE | DP
User.36: This gerber is just for your reference to find the SE impedance traces in layer L1. | SE IMPEDANCE TABLE: L1 | * - Denotes that this Impedance | is NOT used | IMP(Ohm) | *33.0 | *35.0 | *37.5 | *40.0 | *45.0 | 50.0 | *55.0 | WIDTH(mils) | 8.0 | 7.5 | 6.5 | 6.0 | 4.5 | 3.5 | nil | TYPE | SE
User.38: This gerber is just for your reference to find the DP impedance traces in layer L3. | DP IMPEDANCE TABLE: L3 | * - Denotes that this Impedance | is NOT used | IMP(Ohm) | *60.0 | *63.0 | *70.0 | *72.0 | *75.0 | *80.0 | *83.0 | *85.0 | *88.0 | *90.0 | *100.0 | WIDTH(mils) | 10.5/4.5 | 9.5/4.5 | 8.5/4.0 | 9.5/4.0 | 7.0/5.0 | 8.5/5.0 | 7.5/5.0 | 6.5/4.5 | 6.0/4.5 | 5.5/5.0 | 6.0/5.0 | 5.5/4.5 | 5.0/4.0 | 5.0/5.5 | 4.0/4.0 | 5.0/5.0 | 5.0/6.0 | 4.0/4.5 | 4.0/6.5 | 4.0/10.0 | TYPE | DP
User.40: This gerber is just for your reference to find the SE impedance traces in layer L3. | SE IMPEDANCE TABLE: L3 | * - Denotes that this Impedance | is NOT used | IMP(Ohm) | *33.0 | *35.0 | *37.5 | *40.0 | *45.0 | *50.0 | *55.0 | WIDTH(mils) | 11.0 | 9.0 | 10.0 | 8.5 | 7.5 | 6.5 | 8.0 | 5.0 | 4.0 | TYPE | SE
User.42: This gerber is just for your reference to find the DP impedance traces in layer L4. | DP IMPEDANCE TABLE: L4 | * - Denotes that this Impedance | is NOT used | IMP(Ohm) | *60.0 | *63.0 | *70.0 | *72.0 | *75.0 | *80.0 | *83.0 | *85.0 | *88.0 | *90.0 | *100.0 | WIDTH(mils) | 10.5/4.5 | 9.5/4.0 | 8.5/5.0 | 7.5/5.0 | 7.0/5.0 | 6.0/5.0 | 5.5/4.5 | 5.5/5.0 | 5.0/5.0 | 5.0/6.0 | 4.0/6.5 | TYPE | DP
User.44: This gerber is just for your reference to find the SE impedance traces in layer L4. | SE IMPEDANCE TABLE: L4 | * - Denotes that this Impedance | is NOT used | IMP(Ohm) | *33.0 | *35.0 | *37.5 | *40.0 | *45.0 | *50.0 | *55.0 | WIDTH(mils) | 11.0 | 10.0 | 9.0 | 8.0 | 6.5 | 5.0 | 4.0 | TYPE | SE
User.45: Note:Refer to DRILL layer for ELLIPSE drill direction | FIGURE | SIZE | 10.0 | 16.0 | 86.0 | 119.0 | DRILL CHART: TOP to BOTTOM | ALL UNITS ARE IN MILS | PLATED | NON-PLATED | QTY | 194 | 4 | 2 | This gerber is just for your reference to find the SE impedance traces in layer L6. | This gerber is just for your reference to find the SE impedance traces in layer L8. | This gerber is just for your reference to find the DP impedance traces in layer L6. | This gerber is just for your reference to find the DP impedance traces in layer L8. | DP IMPEDANCE TABLE: L6 | DP IMPEDANCE TABLE: L8 | SE IMPEDANCE TABLE: L6 | SE IMPEDANCE TABLE: L8 | * - Denotes that this Impedance | is NOT used | Starlord13 Keyboard | Model | IMP(Ohm) | *33.0 | *60.0 | *35.0 | *63.0 | *37.5 | *70.0 | *40.0 | *72.0 | *45.0 | *75.0 | *80.0 | 50.0 | *55.0 | *83.0 | *85.0 | *88.0 | *90.0 | *100.0 | PCB_NO | 15897 | VER. | SB | WIDTH(mils) | 8.0 | 9.0 | 7.5 | 8.5 | 6.5 | 6.0 | 4.5 | 5.0 | 3.5 | 4.0 | nil | 7.5/4.0 | 7.0/4.5 | 6.0/5.0 | 5.5/4.5 | 5.0/4.5 | 4.5/5.0 | 3.5/4.0 | 4.0/5.0 | 4.0/7.0 | 4.0/8.0 | 3.5/6.0 | 9.5/4.5 | 8.5/4.0 | 7.0/5.0 | 6.5/4.5 | 6.0/4.5 | 5.5/5.0 | 5.0/4.0 | 5.0/5.5 | 4.0/4.0 | 4.0/4.5 | 4.0/10.0 | Layer | DRILL | L1 | L2GND | L3 | L4 | TMASK | TPLACE | TSILK | TSMD | TYPE | SE | DP | Designer | JAZZ_XUE | Date | 12/02/2015 | BMASK | BPLACE | BSILK | BSMD | L5VCC | L6 | L7GND | L8
